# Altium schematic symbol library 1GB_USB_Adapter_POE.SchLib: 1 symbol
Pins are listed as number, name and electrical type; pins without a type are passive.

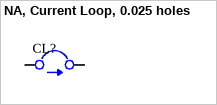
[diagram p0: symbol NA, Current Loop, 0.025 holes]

## NA, Current Loop, 0.025 holes
designator CL?  (value not drawn)
NA, Current Loop, 0.025 holes
footprint CURLOOP_25-DIA
pins: 1, 2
